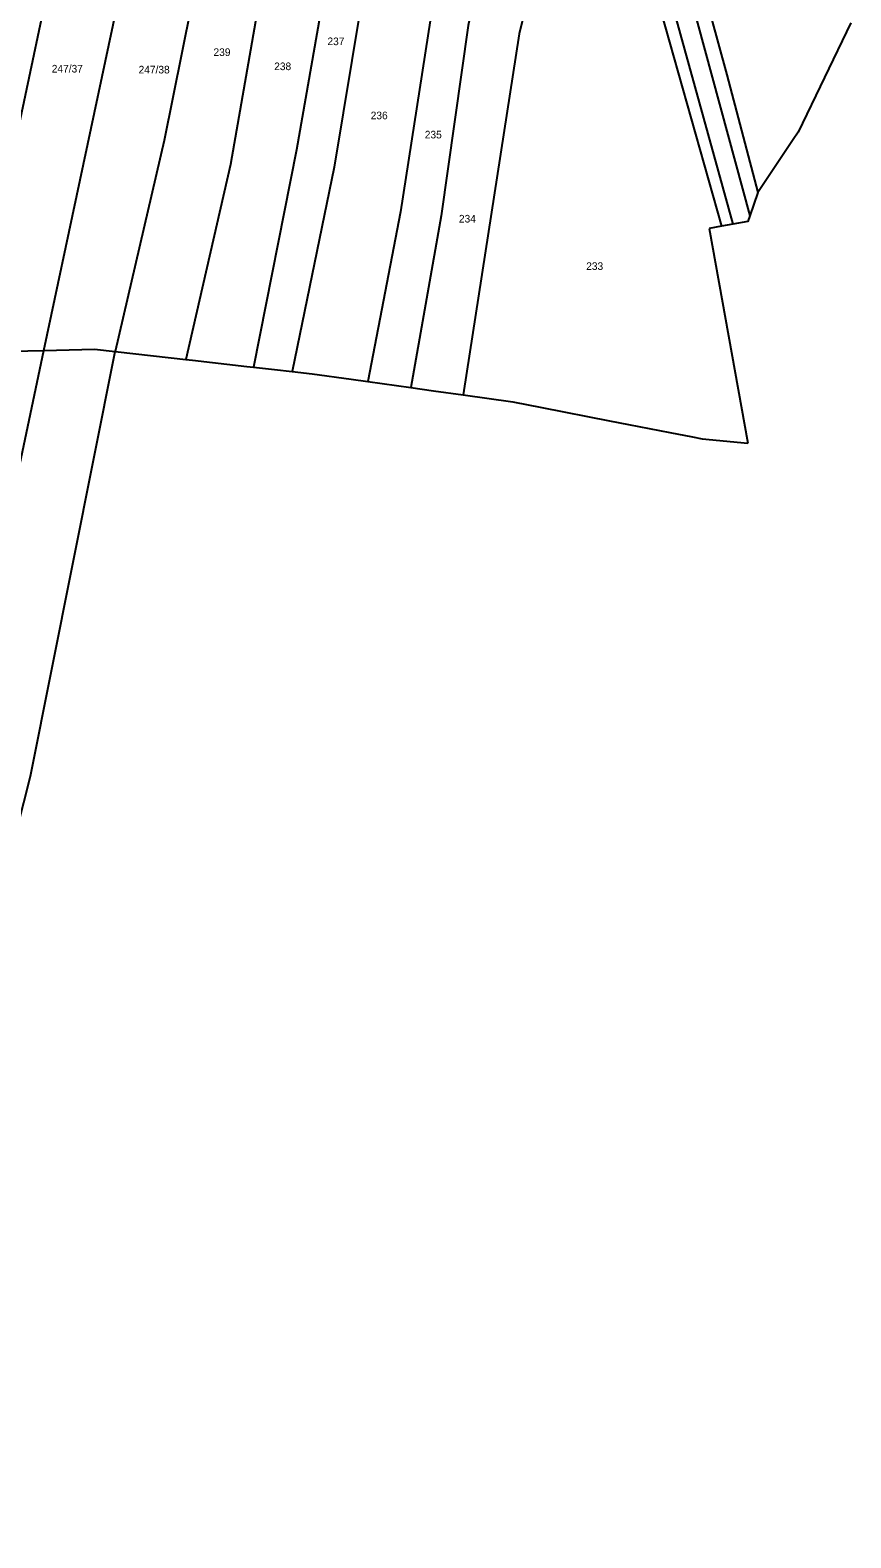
# Model space of a CAD drawing. Extents: x -744566 to -741843, y -1128407 to -1126744.
# Drawn here: x -742899.7 to -742716.4, y -1128361.2 to -1128024.5 of the extents above; entities that cross this region are included whole.
import ezdxf

# ---------------------------------------------------------------- set-up
doc = ezdxf.new("R2010")
doc.units = 0
for name, color, linetype in [('Hranice parcel', 7, 'Continuous'), ('Parcelní čísla', 7, 'Continuous'), ('Vnitřní kresba', 7, 'Continuous')]:
    doc.layers.add(name, color=color, linetype=linetype)

msp = doc.modelspace()

# ---------------------------------------------------------------- linework, layer by layer
at = {"layer": 'Hranice parcel'}
for p, q in [((-742772.05, -1127973.74), (-742745.25, -1128068.29)), ((-742716.39, -1128022.92), (-742728.18, -1128047.33)), ((-742728.18, -1128047.33), (-742729.28, -1128048.97)), ((-742729.28, -1128048.97), (-742737.18, -1128060.8)), ((-742745.25, -1128068.29), (-742748.02, -1128068.81)), ((-742748.02, -1128068.81), (-742739.36, -1128116.8)), ((-742912.92, -1128096.44), (-742896.59, -1128096.06)), ((-742880.65, -1128096.32), (-742872.14, -1128097.28)), ((-742872.14, -1128097.28), (-742864.87, -1128098.1)), ((-742864.87, -1128098.1), (-742863.41, -1128098.26)), ((-742863.41, -1128098.26), (-742851.3, -1128099.63)), ((-742851.3, -1128099.63), (-742849.78, -1128099.8)), ((-742849.78, -1128099.8), (-742845.11, -1128100.32)), ((-742845.11, -1128100.32), (-742841.14, -1128100.77)), ((-742841.14, -1128100.77), (-742836.67, -1128101.27)), ((-742836.67, -1128101.27), (-742827.97, -1128102.49)), ((-742827.97, -1128102.49), (-742824.28, -1128103)), ((-742824.28, -1128103), (-742814.65, -1128104.35)), ((-742814.65, -1128104.35), (-742809.56, -1128105.06)), ((-742809.56, -1128105.06), (-742802.94, -1128105.99)), ((-742802.94, -1128105.99), (-742791.91, -1128107.53)), ((-742791.91, -1128107.53), (-742785.41, -1128108.8)), ((-742785.41, -1128108.8), (-742770.28, -1128111.77)), ((-742770.28, -1128111.77), (-742766.05, -1128112.6)), ((-742766.05, -1128112.6), (-742756.81, -1128114.41)), ((-742756.81, -1128114.41), (-742751.78, -1128115.4))]:
    msp.add_line(p, q, dxfattribs=at)
for points in [[(-742912.92, -1128096.44), (-742883.88, -1127959.44), (-742866.58, -1127888.59), (-742858.3, -1127862.06), (-742854.64, -1127854.03)], [(-742896.59, -1128096.06), (-742872.27, -1127981.64), (-742851.64, -1127891.97), (-742840.94, -1127866.29)], [(-742829.62, -1127879.49), (-742835.64, -1127895.32), (-742843.58, -1127923.46), (-742855.73, -1127979.68), (-742869.71, -1128049.18), (-742880.65, -1128096.32)], [(-742818.84, -1127892.78), (-742824.75, -1127907.89), (-742842.47, -1127983.35), (-742854.91, -1128054.54), (-742864.87, -1128098.1)], [(-742808.46, -1127906.18), (-742818.57, -1127939.73), (-742825.08, -1127964.96), (-742840.18, -1128051.28), (-742849.78, -1128099.8)], [(-742800.6, -1127916.58), (-742810.82, -1127945.91), (-742817.85, -1127971.05), (-742831.77, -1128055.15), (-742841.14, -1128100.77)], [(-742775.86, -1127934.72), (-742770.7, -1127945.05), (-742763.59, -1127963.24), (-742744.12, -1128034.5), (-742737.18, -1128060.8)], [(-742785.19, -1127941), (-742799.05, -1127970.68), (-742806.6, -1127998.43), (-742816.93, -1128065.15), (-742824.28, -1128103)], [(-742777.55, -1127957.37), (-742787.96, -1127974.34), (-742797.26, -1128001.5), (-742801.83, -1128023.54), (-742807.9, -1128066.04), (-742814.65, -1128104.35)], [(-742772.05, -1127973.74), (-742780.73, -1127990.76), (-742787.24, -1128012.25), (-742790.44, -1128025.37), (-742802.94, -1128105.99)], [(-742737.18, -1128060.8), (-742738.98, -1128066.02), (-742739.4, -1128067.25), (-742742.76, -1128067.85), (-742745.25, -1128068.29)], [(-742964.35, -1128361.25), (-742945.14, -1128295.68), (-742915.26, -1128185.79), (-742907.81, -1128148.82), (-742896.59, -1128096.06)], [(-742943.65, -1128350.72), (-742918.75, -1128266.43), (-742899.56, -1128191.16), (-742880.65, -1128096.32)], [(-742896.59, -1128096.06), (-742885.31, -1128095.8), (-742880.65, -1128096.32)], [(-742751.78, -1128115.4), (-742749.59, -1128115.83), (-742739.36, -1128116.8)]]:
    msp.add_lwpolyline(points, dxfattribs=at)
at = {"layer": 'Vnitřní kresba'}
for p, q in [((-742771.04, -1127965.41), (-742742.76, -1128067.85)), ((-742766.43, -1127964.48), (-742738.98, -1128066.02))]:
    msp.add_line(p, q, dxfattribs=at)

# ---------------------------------------------------------------- texts
at = {"layer": 'Parcelní čísla'}
for s, p in [('237', (-742833.28, -1128027.89)), ('239', (-742858.73, -1128030.31)), ('247/37', (-742894.85, -1128034)), ('247/38', (-742875.46, -1128034.21)), ('238', (-742845.17, -1128033.47)), ('236', (-742823.62, -1128044.44)), ('235', (-742811.54, -1128048.72)), ('234', (-742803.92, -1128067.5)), ('233', (-742775.49, -1128078.09))]:
    msp.add_text(s, height=1.7, dxfattribs=at).set_placement(p)

doc.saveas('drawing.dxf')
